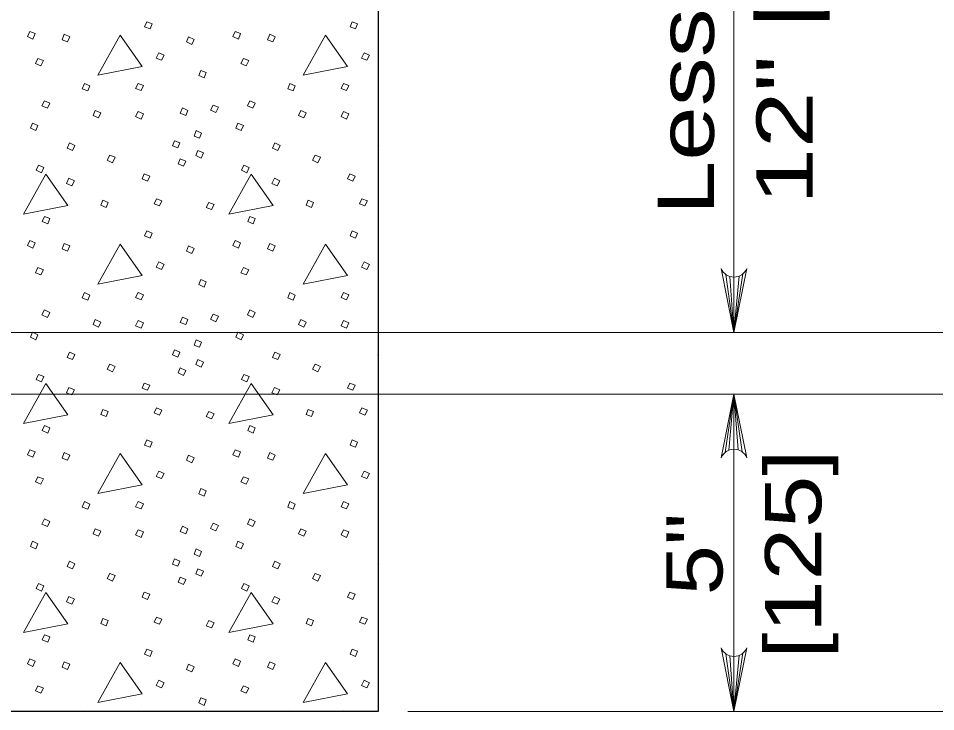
# Model space of a CAD drawing. Extents: x 1036.7 to 1070.7, y 883.9 to 905.9.
# Drawn here: x 1042.7 to 1045.244, y 893.81 to 895.731 of the extents above; entities that cross this region are included whole.
import ezdxf
from ezdxf.enums import TextEntityAlignment as Align

# ---------------------------------------------------------------- set-up
doc = ezdxf.new("R2010")
doc.units = 0
doc.header["$LTSCALE"] = 0.062
doc.layers.add('1', color=7, linetype='Continuous', lineweight=13)

msp = doc.modelspace()

# ---------------------------------------------------------------- linework, layer by layer
at = {"layer": '1', "lineweight": 25}
msp.add_line((1043.69742, 899.48867), (1043.69742, 893.80992), dxfattribs=at)
at = {"layer": '1'}
for p, q in [((1044.68467, 895.50617), (1044.68467, 896.67133)), ((1044.68467, 895.50617), (1044.68467, 894.86117)), ((1044.66225, 895.02142), (1044.68467, 894.86117)), ((1044.67333, 895.01592), (1044.68467, 894.86117)), ((1044.7095, 895.02325), (1044.68467, 894.86117)), ((1044.69908, 895.01717), (1044.68467, 894.86117)), ((1044.68467, 895.01433), (1044.68467, 894.86117)), ((1045.865, 894.86117), (1041.94258, 894.86117)), ((1046.23192, 894.69025), (1041.88933, 894.69025)), ((1044.65992, 894.52808), (1044.68467, 894.69025)), ((1044.67025, 894.53425), (1044.68467, 894.69025)), ((1044.68467, 894.53708), (1044.68467, 894.69025)), ((1044.696, 894.53542), (1044.68467, 894.69025)), ((1044.70708, 894.53), (1044.68467, 894.69025)), ((1044.7095, 893.972), (1044.68467, 893.80992)), ((1044.66225, 893.97017), (1044.68467, 893.80992)), ((1044.67333, 893.96475), (1044.68467, 893.80992)), ((1044.69908, 893.96592), (1044.68467, 893.80992)), ((1044.68467, 893.96308), (1044.68467, 893.80992)), ((1042.88208, 893.80992), (1042.883, 893.81225)), ((1042.883, 893.81225), (1042.888, 893.80992)), ((1043.03083, 893.80992), (1043.032, 893.81225)), ((1043.032, 893.81225), (1043.03783, 893.80992)), ((1043.45183, 893.80992), (1043.45275, 893.81225)), ((1043.45275, 893.81225), (1043.45775, 893.80992)), ((1043.6005, 893.80992), (1043.60167, 893.81225)), ((1043.60167, 893.81225), (1043.6075, 893.80992)), ((1045.65908, 893.80992), (1043.78042, 893.80992))]:
    msp.add_line(p, q, dxfattribs=at)
for points in [[(1043.05592, 895.72217), (1043.07092, 895.71617), (1043.06492, 895.70217), (1043.04992, 895.70817)], [(1043.62567, 895.72217), (1043.64067, 895.71617), (1043.63467, 895.70217), (1043.61967, 895.70817)], [(1042.73108, 895.69517), (1042.74608, 895.68917), (1042.74008, 895.67417), (1042.72508, 895.68117)], [(1042.82708, 895.68717), (1042.84208, 895.68017), (1042.83608, 895.66617), (1042.82108, 895.67217)], [(1042.982, 895.68517), (1042.92, 895.57425), (1043.043, 895.59825)], [(1043.17192, 895.68017), (1043.18692, 895.67317), (1043.18092, 895.65917), (1043.16592, 895.66617)], [(1043.30083, 895.69517), (1043.31583, 895.68917), (1043.30983, 895.67417), (1043.29483, 895.68117)], [(1043.39675, 895.68717), (1043.41175, 895.68017), (1043.40575, 895.66617), (1043.39083, 895.67217)], [(1043.55175, 895.68517), (1043.48975, 895.57425), (1043.61267, 895.59825)], [(1043.08892, 895.63617), (1043.10392, 895.62917), (1043.09692, 895.61517), (1043.08192, 895.62117)], [(1043.65867, 895.63617), (1043.67367, 895.62917), (1043.66667, 895.61517), (1043.65167, 895.62117)], [(1042.75408, 895.62017), (1042.76908, 895.61417), (1042.76208, 895.60025), (1042.74708, 895.60617)], [(1043.32383, 895.62017), (1043.33883, 895.61417), (1043.33183, 895.60025), (1043.31683, 895.60617)], [(1043.20592, 895.58725), (1043.22083, 895.58125), (1043.21492, 895.56625), (1043.19992, 895.57325)], [(1042.883, 895.55125), (1042.898, 895.54425), (1042.892, 895.53025), (1042.877, 895.53625)], [(1043.032, 895.55125), (1043.04692, 895.54525), (1043.03992, 895.53125), (1043.025, 895.53725)], [(1043.45275, 895.55125), (1043.46775, 895.54425), (1043.46175, 895.53025), (1043.44675, 895.53625)], [(1043.60167, 895.55125), (1043.61667, 895.54525), (1043.60967, 895.53125), (1043.59467, 895.53725)], [(1042.77208, 895.50325), (1042.78708, 895.49625), (1042.78008, 895.48225), (1042.76508, 895.48925)], [(1043.34183, 895.50325), (1043.35683, 895.49625), (1043.34983, 895.48225), (1043.33483, 895.48925)], [(1042.913, 895.47625), (1042.928, 895.46925), (1042.922, 895.45533), (1042.907, 895.46225)], [(1043.032, 895.47325), (1043.04692, 895.46725), (1043.03992, 895.45225), (1043.025, 895.45925)], [(1043.15492, 895.48325), (1043.16992, 895.47625), (1043.16392, 895.46225), (1043.14892, 895.46825)], [(1043.23983, 895.49125), (1043.25483, 895.48525), (1043.24783, 895.47025), (1043.23283, 895.47725)], [(1043.48275, 895.47625), (1043.49775, 895.46925), (1043.49175, 895.45533), (1043.47675, 895.46225)], [(1043.60167, 895.47325), (1043.61667, 895.46725), (1043.60967, 895.45225), (1043.59467, 895.45925)], [(1042.73908, 895.44133), (1042.75408, 895.43433), (1042.74808, 895.42033), (1042.73308, 895.42733)], [(1043.30883, 895.44133), (1043.32383, 895.43433), (1043.31783, 895.42033), (1043.30283, 895.42733)], [(1043.19292, 895.42033), (1043.20792, 895.41333), (1043.20192, 895.39933), (1043.18692, 895.40533)], [(1042.84108, 895.38633), (1042.85608, 895.37933), (1042.85008, 895.36533), (1042.83508, 895.37133)], [(1043.13292, 895.39233), (1043.14792, 895.38633), (1043.14192, 895.37233), (1043.12692, 895.37833)], [(1043.41075, 895.38633), (1043.42575, 895.37933), (1043.41975, 895.36533), (1043.40475, 895.37133)], [(1042.953, 895.35233), (1042.968, 895.34633), (1042.961, 895.33133), (1042.946, 895.33833)], [(1043.19792, 895.36533), (1043.21292, 895.35833), (1043.20692, 895.34433), (1043.19192, 895.35133)], [(1043.52275, 895.35233), (1043.53775, 895.34633), (1043.53075, 895.33133), (1043.51575, 895.33833)], [(1042.75508, 895.32433), (1042.77008, 895.31833), (1042.76408, 895.30342), (1042.74908, 895.31033)], [(1043.14892, 895.34233), (1043.16392, 895.33533), (1043.15792, 895.32133), (1043.14292, 895.32833)], [(1043.32483, 895.32433), (1043.33983, 895.31833), (1043.33383, 895.30342), (1043.31883, 895.31033)], [(1042.77608, 895.29942), (1042.71408, 895.18842), (1042.83708, 895.21242)], [(1043.04892, 895.30042), (1043.06392, 895.29442), (1043.05792, 895.28042), (1043.043, 895.28642)], [(1043.34583, 895.29942), (1043.28383, 895.18842), (1043.40675, 895.21242)], [(1043.61867, 895.30042), (1043.63367, 895.29442), (1043.62767, 895.28042), (1043.61267, 895.28642)], [(1042.84008, 895.28842), (1042.85508, 895.28142), (1042.84808, 895.26742), (1042.83308, 895.27342)], [(1043.40975, 895.28842), (1043.42475, 895.28142), (1043.41775, 895.26742), (1043.40275, 895.27342)], [(1042.934, 895.22742), (1042.949, 895.22142), (1042.943, 895.20742), (1042.928, 895.21342)], [(1043.08292, 895.23142), (1043.09792, 895.22542), (1043.09092, 895.21142), (1043.07592, 895.21742)], [(1043.22783, 895.22142), (1043.24283, 895.21542), (1043.23583, 895.20142), (1043.22083, 895.20742)], [(1043.50375, 895.22742), (1043.51875, 895.22142), (1043.51275, 895.20742), (1043.49775, 895.21342)], [(1043.65267, 895.23142), (1043.66767, 895.22542), (1043.66067, 895.21142), (1043.64567, 895.21742)], [(1042.77208, 895.18242), (1042.78708, 895.17642), (1042.78108, 895.1615), (1042.76608, 895.1685)], [(1043.34183, 895.18242), (1043.35683, 895.17642), (1043.35083, 895.1615), (1043.33583, 895.1685)], [(1043.05592, 895.1425), (1043.07092, 895.1365), (1043.06492, 895.1225), (1043.04992, 895.1285)], [(1043.62567, 895.1425), (1043.64067, 895.1365), (1043.63467, 895.1225), (1043.61967, 895.1285)], [(1042.73108, 895.1155), (1042.74608, 895.1095), (1042.74008, 895.0945), (1042.72508, 895.1015)], [(1042.82708, 895.1075), (1042.84208, 895.1005), (1042.83608, 895.0865), (1042.82108, 895.0925)], [(1042.982, 895.1055), (1042.92, 894.99458), (1043.043, 895.01858)], [(1043.17192, 895.1005), (1043.18692, 895.0935), (1043.18092, 895.0795), (1043.16592, 895.0865)], [(1043.30083, 895.1155), (1043.31583, 895.1095), (1043.30983, 895.0945), (1043.29483, 895.1015)], [(1043.39675, 895.1075), (1043.41175, 895.1005), (1043.40575, 895.0865), (1043.39083, 895.0925)], [(1043.55175, 895.1055), (1043.48975, 894.99458), (1043.61267, 895.01858)], [(1042.75408, 895.0405), (1042.76908, 895.0345), (1042.76208, 895.0205), (1042.74708, 895.0265)], [(1043.08892, 895.0565), (1043.10392, 895.0495), (1043.09692, 895.0355), (1043.08192, 895.0415)], [(1043.32383, 895.0405), (1043.33883, 895.0345), (1043.33183, 895.0205), (1043.31683, 895.0265)], [(1043.65867, 895.0565), (1043.67367, 895.0495), (1043.66667, 895.0355), (1043.65167, 895.0415)], [(1043.20592, 895.00758), (1043.22083, 895.00158), (1043.21492, 894.98658), (1043.19992, 894.99358)], [(1042.883, 894.97158), (1042.898, 894.96458), (1042.892, 894.95058), (1042.877, 894.95658)], [(1043.032, 894.97158), (1043.04692, 894.96558), (1043.03992, 894.95158), (1043.025, 894.95758)], [(1043.45275, 894.97158), (1043.46775, 894.96458), (1043.46175, 894.95058), (1043.44675, 894.95658)], [(1043.60167, 894.97158), (1043.61667, 894.96558), (1043.60967, 894.95158), (1043.59467, 894.95758)], [(1042.77208, 894.92358), (1042.78708, 894.91658), (1042.78008, 894.90258), (1042.76508, 894.90958)], [(1043.34183, 894.92358), (1043.35683, 894.91658), (1043.34983, 894.90258), (1043.33483, 894.90958)], [(1042.913, 894.89658), (1042.928, 894.88958), (1042.922, 894.87567), (1042.907, 894.88258)], [(1043.032, 894.89358), (1043.04692, 894.88758), (1043.03992, 894.87267), (1043.025, 894.87958)], [(1043.15492, 894.90358), (1043.16992, 894.89658), (1043.16392, 894.88258), (1043.14892, 894.88858)], [(1043.23983, 894.91158), (1043.25483, 894.90558), (1043.24783, 894.89058), (1043.23283, 894.89758)], [(1043.48275, 894.89658), (1043.49775, 894.88958), (1043.49175, 894.87567), (1043.47675, 894.88258)], [(1043.60167, 894.89358), (1043.61667, 894.88758), (1043.60967, 894.87267), (1043.59467, 894.87958)], [(1042.73908, 894.86167), (1042.75408, 894.85467), (1042.74808, 894.84067), (1042.73308, 894.84767)], [(1043.19292, 894.84067), (1043.20792, 894.83367), (1043.20192, 894.81967), (1043.18692, 894.82567)], [(1043.30883, 894.86167), (1043.32383, 894.85467), (1043.31783, 894.84067), (1043.30283, 894.84767)], [(1043.13292, 894.81267), (1043.14792, 894.80667), (1043.14192, 894.79267), (1043.12692, 894.79867)], [(1042.84108, 894.80667), (1042.85608, 894.79967), (1042.85008, 894.78567), (1042.83508, 894.79167)], [(1043.41075, 894.80667), (1043.42575, 894.79967), (1043.41975, 894.78567), (1043.40475, 894.79167)], [(1042.953, 894.77267), (1042.968, 894.76667), (1042.961, 894.75167), (1042.946, 894.75867)], [(1043.14892, 894.76267), (1043.16392, 894.75567), (1043.15792, 894.74167), (1043.14292, 894.74867)], [(1043.19792, 894.78567), (1043.21292, 894.77867), (1043.20692, 894.76467), (1043.19192, 894.77167)], [(1043.52275, 894.77267), (1043.53775, 894.76667), (1043.53075, 894.75167), (1043.51575, 894.75867)], [(1042.75508, 894.74467), (1042.77008, 894.73867), (1042.76408, 894.72375), (1042.74908, 894.73075)], [(1043.32483, 894.74467), (1043.33983, 894.73867), (1043.33383, 894.72375), (1043.31883, 894.73075)], [(1042.77608, 894.71975), (1042.71408, 894.60875), (1042.83708, 894.63275)], [(1043.04892, 894.72075), (1043.06392, 894.71475), (1043.05792, 894.70075), (1043.043, 894.70675)], [(1043.34583, 894.71975), (1043.28383, 894.60875), (1043.40675, 894.63275)], [(1043.61867, 894.72075), (1043.63367, 894.71475), (1043.62767, 894.70075), (1043.61267, 894.70675)], [(1042.84008, 894.70875), (1042.85508, 894.70175), (1042.84808, 894.68775), (1042.83308, 894.69375)], [(1043.40975, 894.70875), (1043.42475, 894.70175), (1043.41775, 894.68775), (1043.40275, 894.69375)], [(1042.934, 894.64775), (1042.949, 894.64175), (1042.943, 894.62775), (1042.928, 894.63375)], [(1043.08292, 894.65175), (1043.09792, 894.64575), (1043.09092, 894.63175), (1043.07592, 894.63775)], [(1043.22783, 894.64175), (1043.24283, 894.63575), (1043.23583, 894.62175), (1043.22083, 894.62775)], [(1043.50375, 894.64775), (1043.51875, 894.64175), (1043.51275, 894.62775), (1043.49775, 894.63375)], [(1043.65267, 894.65175), (1043.66767, 894.64575), (1043.66067, 894.63175), (1043.64567, 894.63775)], [(1042.77208, 894.60275), (1042.78708, 894.59675), (1042.78108, 894.58183), (1042.76608, 894.58875)], [(1043.34183, 894.60275), (1043.35683, 894.59675), (1043.35083, 894.58183), (1043.33583, 894.58875)], [(1043.05592, 894.56283), (1043.07092, 894.55683), (1043.06492, 894.54283), (1043.04992, 894.54883)], [(1043.62567, 894.56283), (1043.64067, 894.55683), (1043.63467, 894.54283), (1043.61967, 894.54883)], [(1042.73108, 894.53583), (1042.74608, 894.52983), (1042.74008, 894.51483), (1042.72508, 894.52183)], [(1043.30083, 894.53583), (1043.31583, 894.52983), (1043.30983, 894.51483), (1043.29483, 894.52183)], [(1042.82708, 894.52783), (1042.84208, 894.52083), (1042.83608, 894.50683), (1042.82108, 894.51283)], [(1042.982, 894.52583), (1042.92, 894.41492), (1043.043, 894.43892)], [(1043.17192, 894.52083), (1043.18692, 894.51383), (1043.18092, 894.49983), (1043.16592, 894.50683)], [(1043.39675, 894.52783), (1043.41175, 894.52083), (1043.40575, 894.50683), (1043.39083, 894.51283)], [(1043.55175, 894.52583), (1043.48975, 894.41492), (1043.61267, 894.43892)], [(1042.75408, 894.46083), (1042.76908, 894.45483), (1042.76208, 894.44083), (1042.74708, 894.44683)], [(1043.08892, 894.47683), (1043.10392, 894.46983), (1043.09692, 894.45583), (1043.08192, 894.46183)], [(1043.32383, 894.46083), (1043.33883, 894.45483), (1043.33183, 894.44083), (1043.31683, 894.44683)], [(1043.65867, 894.47683), (1043.67367, 894.46983), (1043.66667, 894.45583), (1043.65167, 894.46183)], [(1043.20592, 894.42792), (1043.22083, 894.42192), (1043.21492, 894.40692), (1043.19992, 894.41392)], [(1042.883, 894.39192), (1042.898, 894.38492), (1042.892, 894.37092), (1042.877, 894.37692)], [(1043.032, 894.39192), (1043.04692, 894.38592), (1043.03992, 894.37192), (1043.025, 894.37792)], [(1043.45275, 894.39192), (1043.46775, 894.38492), (1043.46175, 894.37092), (1043.44675, 894.37692)], [(1043.60167, 894.39192), (1043.61667, 894.38592), (1043.60967, 894.37192), (1043.59467, 894.37792)], [(1042.77208, 894.34392), (1042.78708, 894.33692), (1042.78008, 894.32292), (1042.76508, 894.32992)], [(1043.23983, 894.33192), (1043.25483, 894.32592), (1043.24783, 894.31092), (1043.23283, 894.31792)], [(1043.34183, 894.34392), (1043.35683, 894.33692), (1043.34983, 894.32292), (1043.33483, 894.32992)], [(1042.913, 894.31692), (1042.928, 894.30992), (1042.922, 894.296), (1042.907, 894.30292)], [(1043.032, 894.31392), (1043.04692, 894.30792), (1043.03992, 894.293), (1043.025, 894.3)], [(1043.15492, 894.32392), (1043.16992, 894.31692), (1043.16392, 894.30292), (1043.14892, 894.30892)], [(1043.48275, 894.31692), (1043.49775, 894.30992), (1043.49175, 894.296), (1043.47675, 894.30292)], [(1043.60167, 894.31392), (1043.61667, 894.30792), (1043.60967, 894.293), (1043.59467, 894.3)], [(1042.73908, 894.282), (1042.75408, 894.275), (1042.74808, 894.261), (1042.73308, 894.268)], [(1043.30883, 894.282), (1043.32383, 894.275), (1043.31783, 894.261), (1043.30283, 894.268)], [(1043.19292, 894.261), (1043.20792, 894.254), (1043.20192, 894.24), (1043.18692, 894.246)], [(1042.84108, 894.227), (1042.85608, 894.22), (1042.85008, 894.206), (1042.83508, 894.212)], [(1043.13292, 894.233), (1043.14792, 894.227), (1043.14192, 894.213), (1043.12692, 894.219)], [(1043.41075, 894.227), (1043.42575, 894.22), (1043.41975, 894.206), (1043.40475, 894.212)], [(1043.19792, 894.206), (1043.21292, 894.199), (1043.20692, 894.185), (1043.19192, 894.192)], [(1042.953, 894.193), (1042.968, 894.187), (1042.961, 894.172), (1042.946, 894.179)], [(1043.14892, 894.183), (1043.16392, 894.176), (1043.15792, 894.162), (1043.14292, 894.169)], [(1043.52275, 894.193), (1043.53775, 894.187), (1043.53075, 894.172), (1043.51575, 894.179)], [(1042.75508, 894.165), (1042.77008, 894.159), (1042.76408, 894.14408), (1042.74908, 894.15108)], [(1043.32483, 894.165), (1043.33983, 894.159), (1043.33383, 894.14408), (1043.31883, 894.15108)], [(1042.77608, 894.14008), (1042.71408, 894.02908), (1042.83708, 894.05308)], [(1042.84008, 894.12908), (1042.85508, 894.12208), (1042.84808, 894.10808), (1042.83308, 894.11408)], [(1043.04892, 894.14108), (1043.06392, 894.13508), (1043.05792, 894.12108), (1043.043, 894.12708)], [(1043.34583, 894.14008), (1043.28383, 894.02908), (1043.40675, 894.05308)], [(1043.40975, 894.12908), (1043.42475, 894.12208), (1043.41775, 894.10808), (1043.40275, 894.11408)], [(1043.61867, 894.14108), (1043.63367, 894.13508), (1043.62767, 894.12108), (1043.61267, 894.12708)], [(1042.934, 894.06808), (1042.949, 894.06208), (1042.943, 894.04808), (1042.928, 894.05408)], [(1043.08292, 894.07208), (1043.09792, 894.06608), (1043.09092, 894.05208), (1043.07592, 894.05808)], [(1043.22783, 894.06208), (1043.24283, 894.05608), (1043.23583, 894.04208), (1043.22083, 894.04808)], [(1043.50375, 894.06808), (1043.51875, 894.06208), (1043.51275, 894.04808), (1043.49775, 894.05408)], [(1043.65267, 894.07208), (1043.66767, 894.06608), (1043.66067, 894.05208), (1043.64567, 894.05808)], [(1042.77208, 894.02308), (1042.78708, 894.01708), (1042.78108, 894.00217), (1042.76608, 894.00908)], [(1043.34183, 894.02308), (1043.35683, 894.01708), (1043.35083, 894.00217), (1043.33583, 894.00908)], [(1043.05592, 893.98317), (1043.07092, 893.97717), (1043.06492, 893.96317), (1043.04992, 893.96917)], [(1043.62567, 893.98317), (1043.64067, 893.97717), (1043.63467, 893.96317), (1043.61967, 893.96917)], [(1042.73108, 893.95617), (1042.74608, 893.95017), (1042.74008, 893.93517), (1042.72508, 893.94217)], [(1042.82708, 893.94817), (1042.84208, 893.94117), (1042.83608, 893.92717), (1042.82108, 893.93317)], [(1043.30083, 893.95617), (1043.31583, 893.95017), (1043.30983, 893.93517), (1043.29483, 893.94217)], [(1043.39675, 893.94817), (1043.41175, 893.94117), (1043.40575, 893.92717), (1043.39083, 893.93317)], [(1042.982, 893.94617), (1042.92, 893.83525), (1043.043, 893.85925)], [(1043.17192, 893.94117), (1043.18692, 893.93417), (1043.18092, 893.92017), (1043.16592, 893.92717)], [(1043.55175, 893.94617), (1043.48975, 893.83525), (1043.61267, 893.85925)], [(1043.08892, 893.89717), (1043.10392, 893.89017), (1043.09692, 893.87617), (1043.08192, 893.88217)], [(1043.65867, 893.89717), (1043.67367, 893.89017), (1043.66667, 893.87617), (1043.65167, 893.88217)], [(1042.75408, 893.88117), (1042.76908, 893.87517), (1042.76208, 893.86125), (1042.74708, 893.86717)], [(1043.32383, 893.88117), (1043.33883, 893.87517), (1043.33183, 893.86125), (1043.31683, 893.86717)], [(1043.20592, 893.84825), (1043.22083, 893.84225), (1043.21492, 893.82725), (1043.19992, 893.83425)]]:
    msp.add_lwpolyline(points, close=True, dxfattribs=at)
for points in [[(1043.69742, 895.378), (1043.69667, 895.37833), (1043.69742, 895.38008)], [(1044.72008, 895.03817), (1044.68467, 894.86117), (1044.64925, 895.03817)], [(1043.69742, 894.79833), (1043.69667, 894.79867), (1043.69742, 894.80042)], [(1044.64925, 894.51325), (1044.68467, 894.69025), (1044.72008, 894.51325)], [(1044.68467, 894.69025), (1044.68467, 894.10833), (1044.68467, 893.80992)], [(1043.69742, 894.21867), (1043.69667, 894.219), (1043.69742, 894.22075)], [(1044.72008, 893.98692), (1044.68467, 893.80992), (1044.64925, 893.98692)]]:
    msp.add_lwpolyline(points, dxfattribs=at)
at = {"layer": '1', "lineweight": 25}
msp.add_lwpolyline([(1043.69742, 893.80992), (1041.27367, 893.80992), (1039.48992, 893.80992)], dxfattribs=at)
at = {"layer": '1'}
for centre, start, end in [((1044.68465, 895.05243), 202.08782, 337.91395), ((1044.68472, 894.49894), 22.08782, 157.91395), ((1044.68465, 894.0012), 202.08782, 337.91395)]:
    msp.add_arc(centre, 0.0382, start, end, dxfattribs=at)

# ---------------------------------------------------------------- texts
for s, width, p in [('Less than', 1.3, (1044.62892, 895.77413)), ('12" [300]', 1.35, (1044.90292, 895.77417)), ('[125]', 1.25, (1044.92675, 894.24633)), ('5"', 1.2, (1044.65275, 894.24637))]:
    msp.add_text(s, height=0.156, rotation=90, dxfattribs=dict(at, width=width)).set_placement(p, align=Align.CENTER)

doc.saveas('drawing.dxf')
